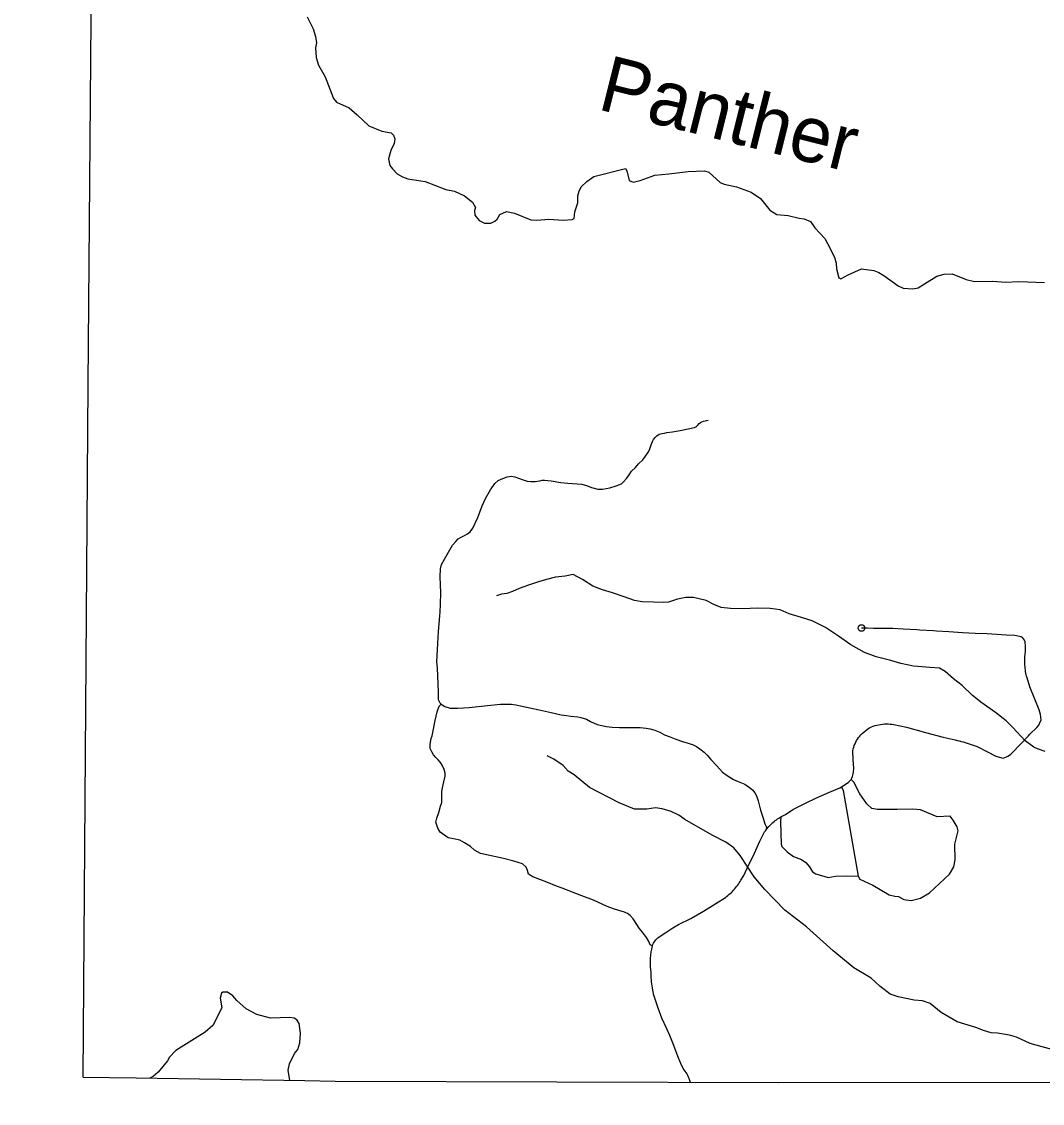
# Model space of a CAD drawing. Extents: x -19 to 366, y -4 to 359.
# Drawn here: x 139.293 to 140.756, y 186.985 to 188.535 of the extents above; entities that cross this region are included whole.
import ezdxf

# ---------------------------------------------------------------- set-up
doc = ezdxf.new("R2010")
doc.units = 0
for name, color, linetype in [('R_Alt Surface', 7, 'Continuous'), ('R_ROW', 7, 'Continuous'), ('R_ROW Annot', 7, 'Continuous'), ('R_Temp Easement', 7, 'Continuous'), ('Sheet Fence', 7, 'Continuous')]:
    doc.layers.add(name, color=color, linetype=linetype)

msp = doc.modelspace()

# ---------------------------------------------------------------- linework, layer by layer
at = {"layer": 'R_Alt Surface'}
for points in [[(139.3808, 187.0227), (139.3884, 188.0149), (139.3927, 188.5383), (139.3933, 189.009), (139.3933, 189.0178), (139.3929, 189.5007)], [(139.3808, 187.0227), (139.457, 187.0215), (139.699, 187.0177), (139.7422, 187.017), (140.378, 187.0152), (140.9038, 187.0155)]]:
    msp.add_lwpolyline(points, dxfattribs=at)
at = {"layer": 'R_ROW'}
for points in [[(140.5764, 187.6635), (140.5567, 187.6647), (140.5416, 187.6654), (140.5279, 187.6656), (140.5139, 187.6657), (140.5052, 187.6662), (140.497, 187.6662)], [(140.4819, 187.4493), (140.483, 187.4512), (140.484, 187.4532), (140.4846, 187.4553), (140.4851, 187.4574), (140.4853, 187.4596), (140.4861, 187.4653), (140.485, 187.4774), (140.4845, 187.4904), (140.485, 187.4929), (140.4858, 187.4954), (140.4866, 187.4978), (140.4876, 187.5002), (140.4887, 187.5025), (140.4899, 187.5048), (140.4913, 187.507), (140.4927, 187.5091), (140.4943, 187.5112), (140.4959, 187.5131), (140.4977, 187.515), (140.506, 187.5219), (140.5086, 187.5233), (140.5111, 187.5244), (140.5137, 187.5254), (140.5163, 187.5263), (140.5189, 187.527), (140.5216, 187.5276), (140.5243, 187.5281), (140.5271, 187.5285), (140.5298, 187.5287), (140.5326, 187.5288), (140.5353, 187.5287), (140.5381, 187.5285), (140.5408, 187.5282), (140.5431, 187.5278), (140.5616, 187.5241), (140.5889, 187.5163), (140.6142, 187.51), (140.6313, 187.5058), (140.6342, 187.5051), (140.6371, 187.5044), (140.64, 187.5037), (140.6428, 187.5029), (140.6457, 187.5021), (140.6485, 187.5012), (140.6514, 187.5003), (140.6542, 187.4994), (140.657, 187.4985), (140.6597, 187.4975), (140.6625, 187.4964), (140.6777, 187.4887), (140.6895, 187.4828), (140.6999, 187.4798), (140.7023, 187.4805), (140.7046, 187.4815), (140.7069, 187.4827), (140.709, 187.484), (140.7109, 187.4856), (140.7128, 187.4874), (140.7361, 187.5118), (140.7384, 187.5142), (140.7482, 187.5236), (140.7513, 187.5269), (140.7523, 187.5293), (140.7544, 187.5346), (140.7535, 187.5421), (140.7516, 187.549), (140.7456, 187.5644), (140.7381, 187.582), (140.7342, 187.5948), (140.7336, 187.5971), (140.733, 187.5993), (140.7326, 187.6015), (140.7322, 187.6038), (140.7319, 187.6061), (140.7316, 187.6083), (140.7314, 187.6106), (140.7312, 187.6129), (140.7311, 187.6152), (140.7311, 187.6175), (140.7311, 187.6198), (140.7312, 187.622), (140.7313, 187.6243), (140.7319, 187.6324), (140.7319, 187.6396), (140.7315, 187.6466), (140.7307, 187.6488), (140.7294, 187.6508), (140.7276, 187.6524), (140.7256, 187.6536), (140.7166, 187.6555), (140.7045, 187.6559), (140.6771, 187.6578), (140.6597, 187.6584), (140.6419, 187.6591), (140.6219, 187.6608), (140.6042, 187.6619), (140.6002, 187.6621), (140.5804, 187.6633), (140.5764, 187.6635)], [(140.468, 187.4387), (140.4765, 187.4439), (140.4783, 187.4452), (140.4799, 187.4467), (140.4819, 187.4493)], [(140.3814, 187.3957), (140.384, 187.3972), (140.3859, 187.3982), (140.3878, 187.3991), (140.3984, 187.4061), (140.4168, 187.4151), (140.4325, 187.4229), (140.451, 187.4308), (140.4657, 187.4374), (140.468, 187.4387)], [(140.3612, 187.3784), (140.364, 187.3816), (140.3654, 187.3831), (140.3669, 187.3846), (140.3684, 187.3861), (140.37, 187.3875), (140.3717, 187.3889), (140.3733, 187.3902), (140.375, 187.3915), (140.3767, 187.3928), (140.3785, 187.3939), (140.3814, 187.3957)], [(140.197, 187.2107), (140.1978, 187.2126), (140.1987, 187.2144), (140.1998, 187.2162), (140.2009, 187.2179), (140.2022, 187.2195), (140.2036, 187.221), (140.205, 187.2224), (140.2066, 187.2237), (140.2176, 187.2308), (140.2263, 187.2364), (140.2347, 187.2413), (140.2521, 187.2499), (140.2702, 187.2605), (140.2883, 187.2715), (140.3017, 187.28), (140.3035, 187.2813), (140.3052, 187.2827), (140.3069, 187.2842), (140.3086, 187.2857), (140.3103, 187.2872), (140.3118, 187.2888), (140.3134, 187.2904), (140.3149, 187.2921), (140.3164, 187.2938), (140.3178, 187.2956), (140.3191, 187.2973), (140.3204, 187.2991), (140.3217, 187.301), (140.3229, 187.3029), (140.3241, 187.3048), (140.3283, 187.3118), (140.3359, 187.3284), (140.3414, 187.3393), (140.351, 187.3606), (140.3568, 187.3724), (140.358, 187.3741), (140.3592, 187.3758), (140.3612, 187.3784)], [(140.197, 187.2107), (140.1957, 187.2062), (140.1953, 187.2042), (140.1951, 187.2021), (140.1941, 187.1926), (140.1938, 187.1801), (140.1948, 187.1729), (140.1949, 187.1708), (140.1949, 187.1679), (140.1951, 187.165), (140.1953, 187.162), (140.1955, 187.1591), (140.1958, 187.1562), (140.1962, 187.1533), (140.1966, 187.1504), (140.1971, 187.1475), (140.1977, 187.1447), (140.1983, 187.1418), (140.199, 187.139), (140.2047, 187.1221), (140.2103, 187.1076), (140.2173, 187.0923), (140.2214, 187.083), (140.2274, 187.0683), (140.2334, 187.052), (140.2383, 187.0403), (140.2424, 187.0333), (140.2451, 187.0294), (140.2463, 187.0274), (140.2474, 187.0254), (140.2485, 187.0232), (140.2494, 187.021), (140.2513, 187.0156)]]:
    msp.add_lwpolyline(points, dxfattribs=at)
msp.add_circle((140.497, 187.6662), 0.00473, dxfattribs=at)
at = {"layer": 'R_ROW Annot'}
for points in [[(139.8942, 187.5571), (139.8929, 187.5586), (139.8919, 187.5603), (139.8911, 187.5622), (139.8905, 187.5642), (139.8904, 187.5747), (139.8888, 187.6087), (139.8883, 187.6178), (139.8891, 187.6352), (139.8905, 187.6613), (139.892, 187.6781), (139.893, 187.6895), (139.8935, 187.7001), (139.8938, 187.7173), (139.8932, 187.7279), (139.8927, 187.7395), (139.8933, 187.7512), (139.8949, 187.7571), (139.899, 187.7647), (139.9106, 187.7849), (139.9151, 187.7903), (139.9188, 187.794), (139.9218, 187.796), (139.9267, 187.7981), (139.9319, 187.8012), (139.9359, 187.8041), (139.9395, 187.8091), (139.9467, 187.8244), (139.9531, 187.8413), (139.9579, 187.8519), (139.965, 187.8643), (139.9712, 187.8731), (139.9759, 187.8777), (139.9825, 187.8805), (139.9889, 187.883), (139.9948, 187.8838), (139.9999, 187.883), (140.0053, 187.881), (140.0117, 187.8786), (140.0178, 187.8766), (140.023, 187.876), (140.0292, 187.8762), (140.0357, 187.8772), (140.0392, 187.8779), (140.0422, 187.8779), (140.0522, 187.8769), (140.066, 187.8745), (140.0761, 187.8736), (140.0893, 187.8729), (140.096, 187.8723), (140.104, 187.8698), (140.1097, 187.8676), (140.1188, 187.8649), (140.1257, 187.8649), (140.1361, 187.867), (140.1452, 187.87), (140.1526, 187.8726), (140.1554, 187.875), (140.1606, 187.8807), (140.163, 187.8843), (140.1647, 187.8873), (140.1673, 187.8909), (140.1731, 187.8962), (140.177, 187.9012), (140.1832, 187.907), (140.1865, 187.9111), (140.1915, 187.9185), (140.1936, 187.923), (140.1955, 187.9285), (140.1974, 187.9332), (140.1988, 187.9365), (140.2009, 187.939), (140.2036, 187.9417), (140.2069, 187.9438), (140.2106, 187.9447), (140.2146, 187.9456), (140.2178, 187.9463), (140.2261, 187.9474), (140.2313, 187.948), (140.2368, 187.949), (140.2577, 187.9535), (140.2604, 187.9548), (140.262, 187.9565), (140.2643, 187.959), (140.2663, 187.9605), (140.2682, 187.9614), (140.2706, 187.9626), (140.2769, 187.964)], [(140.197, 187.2107), (140.1938, 187.2122), (140.1918, 187.2168), (140.1885, 187.2226), (140.1828, 187.2304), (140.178, 187.2363), (140.1748, 187.2416), (140.1697, 187.2493), (140.1653, 187.2541), (140.1616, 187.2569), (140.1572, 187.2589), (140.1488, 187.2614), (140.1413, 187.2638), (140.1321, 187.2674), (140.1128, 187.276), (140.0958, 187.2824), (140.0676, 187.2934), (140.0596, 187.2965), (140.0459, 187.3018), (140.0255, 187.3099), (140.0194, 187.3135), (140.0182, 187.3186), (140.0161, 187.3234), (140.0108, 187.3284), (139.9984, 187.332), (139.9835, 187.3361), (139.9507, 187.3431), (139.9423, 187.348), (139.9362, 187.353), (139.9277, 187.3584), (139.9211, 187.3622), (139.912, 187.3639), (139.9042, 187.3654), (139.8928, 187.3737), (139.8895, 187.3796), (139.8867, 187.3881), (139.8879, 187.3935), (139.8911, 187.4019), (139.8934, 187.4111), (139.895, 187.416), (139.8951, 187.4251), (139.895, 187.4321), (139.8961, 187.4371), (139.898, 187.446), (139.9, 187.454), (139.8999, 187.4583), (139.8985, 187.4635), (139.8959, 187.4698), (139.8933, 187.4736), (139.8901, 187.4772), (139.8864, 187.4807), (139.8831, 187.4844), (139.8808, 187.4886), (139.8785, 187.4935), (139.8786, 187.4996), (139.8801, 187.508), (139.8812, 187.5115), (139.8826, 187.5188), (139.8856, 187.5339), (139.8887, 187.5462), (139.8915, 187.5544), (139.8942, 187.5571)], [(139.8942, 187.5571), (139.8993, 187.5537), (139.907, 187.5514), (139.9184, 187.5514), (139.9344, 187.5524), (139.9607, 187.5552), (139.9793, 187.5569), (139.9897, 187.5571), (139.995, 187.557), (140.0015, 187.5562), (140.0347, 187.549), (140.0522, 187.5452), (140.0663, 187.5418), (140.074, 187.5409), (140.0801, 187.5399), (140.0902, 187.539), (140.0947, 187.538), (140.1024, 187.5355), (140.1083, 187.5323), (140.1181, 187.5281), (140.1244, 187.5263), (140.1306, 187.5251), (140.1396, 187.5242), (140.1501, 187.5237), (140.1652, 187.5236), (140.1795, 187.5234), (140.1884, 187.5225), (140.1939, 187.5217), (140.2005, 187.5199), (140.2076, 187.517), (140.2146, 187.5132), (140.221, 187.5107), (140.2307, 187.5068), (140.2403, 187.5035), (140.2482, 187.5013), (140.2555, 187.4987), (140.2605, 187.4964), (140.2653, 187.4933), (140.2714, 187.4883), (140.2758, 187.4841), (140.281, 187.478), (140.2895, 187.4685), (140.2978, 187.4596), (140.3029, 187.456), (140.308, 187.4523), (140.3132, 187.4493), (140.3203, 187.4464), (140.3295, 187.4423), (140.3365, 187.4378), (140.3404, 187.4342), (140.3438, 187.4299), (140.3462, 187.4255), (140.3486, 187.4184), (140.3522, 187.4053), (140.3559, 187.3935), (140.3584, 187.3858), (140.3601, 187.3817), (140.3612, 187.3784)], [(140.492, 187.3105), (140.4944, 187.3061), (140.5133, 187.2978), (140.5364, 187.2838), (140.5445, 187.2818), (140.5498, 187.2815), (140.5575, 187.2773), (140.5683, 187.2758), (140.5815, 187.2793), (140.5946, 187.2868), (140.6232, 187.3135), (140.6291, 187.324), (140.6311, 187.3338), (140.6308, 187.3565), (140.6356, 187.3758), (140.6341, 187.3811), (140.6284, 187.3907), (140.6238, 187.3968), (140.6056, 187.3958), (140.5813, 187.4058), (140.5706, 187.4068), (140.5479, 187.4061), (140.5198, 187.4062), (140.5118, 187.4077), (140.5045, 187.4142), (140.4943, 187.4286), (140.4857, 187.4452), (140.4819, 187.4493)], [(140.468, 187.4387), (140.4705, 187.4332), (140.492, 187.3105)], [(140.3814, 187.3957), (140.3806, 187.3887), (140.3816, 187.3566), (140.3826, 187.3531), (140.3904, 187.3453), (140.3995, 187.3389), (140.4107, 187.3343), (140.4171, 187.3301), (140.4222, 187.324), (140.4268, 187.317), (140.4314, 187.314), (140.4489, 187.3088), (140.4595, 187.3104), (140.476, 187.3109), (140.492, 187.3105)]]:
    msp.add_lwpolyline(points, dxfattribs=at)
at = {"layer": 'R_Temp Easement'}
for points in [[(139.7023, 188.5419), (139.7106, 188.5245), (139.714, 188.5135), (139.7155, 188.5047), (139.714, 188.4975), (139.7151, 188.4838), (139.7185, 188.4728), (139.728, 188.4561), (139.7401, 188.425), (139.7442, 188.4197), (139.7624, 188.4113), (139.7737, 188.4015), (139.7907, 188.3855), (139.8092, 188.3783), (139.8225, 188.3756), (139.8259, 188.3722), (139.8277, 188.3673), (139.827, 188.3604), (139.8221, 188.3506), (139.8187, 188.3384), (139.8209, 188.3289), (139.8243, 188.324), (139.8311, 188.3168), (139.8387, 188.3126), (139.8463, 188.31), (139.8712, 188.3058), (139.9011, 188.2944), (139.9135, 188.2921), (139.9279, 188.2856), (139.9392, 188.2762), (139.9434, 188.2689), (139.9423, 188.2644), (139.9426, 188.2576), (139.9487, 188.2503), (139.9566, 188.2462), (139.9653, 188.2462), (139.9714, 188.2492), (139.9744, 188.2519), (139.9782, 188.2587), (139.988, 188.2629), (139.9993, 188.2606), (140.0228, 188.2511), (140.0314, 188.2507), (140.0485, 188.2518), (140.0692, 188.2507), (140.0821, 188.2515), (140.0851, 188.253), (140.0859, 188.2625), (140.09, 188.2754), (140.09, 188.2852), (140.0919, 188.2921), (140.0949, 188.2981), (140.1029, 188.3061), (140.1131, 188.3129), (140.1584, 188.3247), (140.1607, 188.3213), (140.1637, 188.3076), (140.1694, 188.305), (140.1796, 188.3072), (140.2008, 188.3148), (140.2208, 188.3171)], [(140.2208, 188.3171), (140.2484, 188.3201), (140.2718, 188.3213), (140.2782, 188.3194), (140.2945, 188.3046), (140.2998, 188.3023), (140.3175, 188.2981), (140.3387, 188.2905), (140.3523, 188.2818), (140.3655, 188.2647), (140.3757, 188.2586), (140.392, 188.2571), (140.4075, 188.2533), (140.4147, 188.2525), (140.4237, 188.2487), (140.4302, 188.2396), (140.4441, 188.2241), (140.4483, 188.2172), (140.4581, 188.1975), (140.4604, 188.1888), (140.4611, 188.1808), (140.4645, 188.1679), (140.4672, 188.1664), (140.4778, 188.1724), (140.4967, 188.1808), (140.5144, 188.1785), (140.5216, 188.1758), (140.5288, 188.1713), (140.5496, 188.1565), (140.5568, 188.1531), (140.5707, 188.1523), (140.5783, 188.1534), (140.587, 188.1595), (140.6051, 188.1701), (140.6153, 188.1732), (140.6271, 188.1735), (140.6471, 188.1656), (140.6588, 188.1625), (140.6849, 188.1633), (140.7038, 188.1618), (140.7227, 188.1629), (140.7593, 188.1614)], [(140.7604, 187.4892), (140.7493, 187.4932), (140.7438, 187.4955), (140.7315, 187.5045), (140.7139, 187.5235), (140.7044, 187.5331), (140.6888, 187.5453), (140.6679, 187.5598), (140.6556, 187.5702), (140.6411, 187.5839), (140.629, 187.5934), (140.617, 187.6038), (140.6086, 187.6087), (140.595, 187.6096), (140.5834, 187.6106), (140.5713, 187.6115), (140.5531, 187.6155), (140.5388, 187.6195), (140.5179, 187.6247), (140.5014, 187.631), (140.4815, 187.6419), (140.464, 187.6544), (140.4454, 187.6667), (140.4261, 187.6765), (140.4111, 187.6813), (140.3932, 187.6866), (140.3802, 187.692), (140.366, 187.6943), (140.3477, 187.6947), (140.3269, 187.6938), (140.3093, 187.6942), (140.2959, 187.6956), (140.2854, 187.6999), (140.274, 187.7055), (140.2561, 187.7101), (140.2451, 187.7098), (140.2331, 187.7075), (140.2202, 187.7032), (140.2126, 187.7026), (140.1988, 187.7033), (140.1824, 187.7035), (140.1716, 187.7055), (140.1567, 187.7109), (140.1398, 187.7168), (140.1255, 187.721), (140.1116, 187.7262), (140.0967, 187.7355), (140.0833, 187.7428), (140.072, 187.7403), (140.0581, 187.7392), (140.0453, 187.7355), (140.0337, 187.7324), (140.0196, 187.7275), (140.0063, 187.7227), (139.9966, 187.7183), (139.9883, 187.7156), (139.9808, 187.7145), (139.9735, 187.7123)], [(140.7091, 187.0829), (140.692, 187.0859), (140.683, 187.0863), (140.672, 187.0893), (140.6607, 187.0939), (140.6342, 187.1019), (140.6112, 187.1155), (140.5953, 187.1284), (140.5843, 187.1322), (140.5726, 187.133), (140.5496, 187.1379), (140.5379, 187.1414), (140.5231, 187.1528), (140.511, 187.1645), (140.4861, 187.1793), (140.4562, 187.2036), (140.4181, 187.2378), (140.3871, 187.2617), (140.3583, 187.2917), (140.3428, 187.3096), (140.3228, 187.3403), (140.3137, 187.351), (140.3024, 187.3593), (140.2828, 187.3692), (140.2438, 187.3916), (140.2351, 187.398), (140.2238, 187.4034), (140.2109, 187.4072), (140.2015, 187.4083), (140.189, 187.4064), (140.1713, 187.4064), (140.1497, 187.4155), (140.107, 187.4379), (140.0851, 187.4558), (140.0764, 187.4611), (140.0692, 187.4691), (140.0556, 187.4785), (140.0462, 187.4831)], [(139.6775, 187.018), (139.675, 187.0326), (139.6766, 187.0417), (139.6841, 187.0565), (139.689, 187.0625), (139.6917, 187.0717), (139.6928, 187.0857), (139.6905, 187.0994), (139.6875, 187.1047), (139.6834, 187.107), (139.6773, 187.1081), (139.6497, 187.1073), (139.6301, 187.1123), (139.6146, 187.1206), (139.6014, 187.1324), (139.5957, 187.1392), (139.5881, 187.1442), (139.5813, 187.1442), (139.5791, 187.143), (139.5775, 187.1358), (139.5798, 187.1222), (139.567, 187.0967), (139.556, 187.0869), (139.5137, 187.0607), (139.5046, 187.0512), (139.502, 187.0462), (139.4883, 187.0299), (139.4819, 187.0239), (139.4764, 187.0212)], [(140.7786, 187.0597), (140.7389, 187.0711), (140.7189, 187.0798), (140.7091, 187.0829)]]:
    msp.add_lwpolyline(points, dxfattribs=at)
at = {"layer": 'Sheet Fence'}
for points in [[(146.7783, 1.697), (146.5788, 10.3131), (146.3785, 18.9294), (146.1776, 27.5458), (145.9759, 36.1624), (145.7736, 44.7791), (145.5705, 53.396), (145.3668, 62.013), (145.1624, 70.6301), (144.9572, 79.2474), (144.7514, 87.8648), (144.5449, 96.4823), (144.3377, 105.1), (144.1299, 113.7179), (143.9213, 122.3359), (143.712, 130.954), (143.5021, 139.5723), (143.2915, 148.1907), (143.0802, 156.8092), (142.8682, 165.4279), (142.6555, 174.0468), (142.4422, 182.6658), (142.2282, 191.2849), (142.0135, 199.9042), (141.7981, 208.5236), (141.582, 217.1432), (141.3653, 225.7629), (141.1479, 234.3828), (140.9298, 243.0028), (140.711, 251.623), (140.4916, 260.2433), (140.2715, 268.8638), (140.0508, 277.4844), (139.8293, 286.1051), (139.6072, 294.726), (139.3845, 303.3471), (139.161, 311.9683), (138.937, 320.5896), (138.7122, 329.2111), (138.4868, 337.8328), (138.2607, 346.4546)], [(139.4406, 1.5315), (139.2511, 10.1473), (139.0608, 18.7633), (138.8699, 27.3793), (138.6784, 35.9956), (138.4861, 44.6119), (138.2932, 53.2285), (138.0997, 61.8451), (137.9055, 70.4619), (137.7106, 79.0789), (137.5151, 87.6959), (137.319, 96.3132), (137.1221, 104.9306), (136.9247, 113.5481), (136.7265, 122.1658), (136.5278, 130.7836), (136.3283, 139.4016), (136.1282, 148.0197), (135.9275, 156.6379), (135.7261, 165.2564), (135.5241, 173.8749), (135.3214, 182.4936), (135.1181, 191.1125), (134.9141, 199.7315), (134.7095, 208.3506), (134.5043, 216.9699), (134.2984, 225.5894), (134.0919, 234.209), (133.8847, 242.8288), (133.6769, 251.4487), (133.4685, 260.0687), (133.2594, 268.6889), (133.0497, 277.3093), (132.8393, 285.9298), (132.6283, 294.5504), (132.4167, 303.1713), (132.2044, 311.7922), (131.9916, 320.4133), (131.778, 329.0346), (131.5639, 337.656), (131.3491, 346.2776)], [(0, 180.8999), (7.1228, 180.9044), (14.2457, 180.9176), (21.3685, 180.9397), (28.4912, 180.9706), (35.614, 181.0103), (42.7366, 181.0589), (49.8592, 181.1163), (56.9818, 181.1825), (64.1042, 181.2575), (71.2266, 181.3414), (78.3488, 181.4341), (85.4709, 181.5357), (92.5929, 181.646), (99.7147, 181.7652), (106.8364, 181.8933), (113.9579, 182.0301), (121.0793, 182.1758), (128.2005, 182.3303), (135.3214, 182.4936), (142.4422, 182.6658), (149.5627, 182.8468), (156.683, 183.0366), (163.8031, 183.2352), (170.9229, 183.4427), (178.0425, 183.659), (185.1617, 183.8841), (192.2807, 184.1181), (199.3994, 184.3608), (206.5178, 184.6124), (213.6359, 184.8728), (220.7537, 185.1421), (227.8711, 185.4201), (234.9881, 185.707), (242.1048, 186.0027), (249.2212, 186.3073), (256.3371, 186.6206), (263.4526, 186.9428), (270.5678, 187.2738), (277.6825, 187.6136), (284.7968, 187.9622), (291.9107, 188.3197), (299.0241, 188.6859), (306.1371, 189.061), (313.2495, 189.4449), (320.3615, 189.8377), (327.4731, 190.2392), (334.5841, 190.6495), (341.6946, 191.0687)]]:
    msp.add_spline(points, degree=3, dxfattribs=at)

# ---------------------------------------------------------------- texts
at = {"layer": 'R_Temp Easement'}
msp.add_text('Panther', height=0.08, rotation=345.9544, dxfattribs=at).set_placement((140.1165, 188.4099))

doc.saveas('drawing.dxf')
